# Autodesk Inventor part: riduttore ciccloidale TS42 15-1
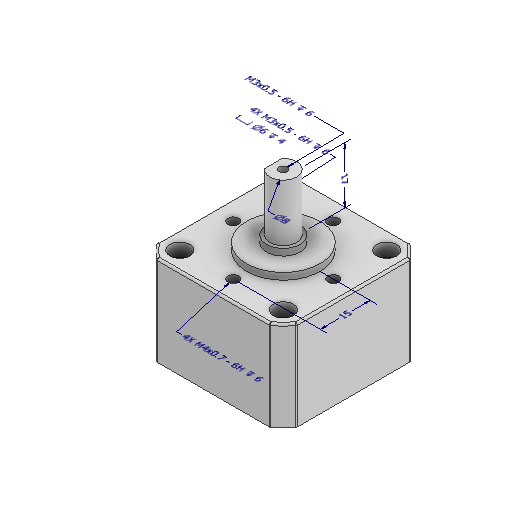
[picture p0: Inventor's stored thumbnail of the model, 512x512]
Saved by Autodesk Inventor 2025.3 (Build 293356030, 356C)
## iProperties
Created: 2026-03
Part Number: riduttore ciccloidale TS42 15-1
Material: Generico
Document SubType Name: Modeling
Designer: R5800u
Density: 1 g/cm^3
Appearance: Default
Author: R5800u
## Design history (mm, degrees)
node "Annotazioni"
  node "Quota diametro 1" dims "d11" = 17, "d58" = 8 (derived)
  node "Nota foro 1" dims "d11" = 17
  node "Nota foro 3" dims "d11" = 17
  node "Quota lineare 1" dims "d11" = 17, "d67" = 17 (derived)
  node "Quota lineare 2" dims "d11" = 17, "d69" = 15 (derived)
  node "Nota foro 4" dims "d11" = 17
  node "Quota lineare 3" dims "d11" = 17, "d73" = 27 (derived)
sketch "Schizzo1"
  geometry: L1 (21, -21)-(-21, -21); L2 (-21, -21)-(-21, 21); L3 (-21, 21)-(21, 21); L4 (21, 21)-(21, -21); L5 (21, -21)-(-21, 21); L6 (-21, -21)-(21, 21); 1 further point
  constraints: 12 end point, 2 midpoint, 2 parallel, 1 horizontal, 1 perpendicular
  dimensions: "d0" = 42 distance of L2.end L3.end; "d1" = 42 distance of L1.end L2.end
extrude "Estrusione1" new body sketch "Schizzo1" distance "d2" = 27; taper "d3" = 0 deg
sketch "Schizzo2"
  geometry: C1 r 11 at (0, 0); 1 further point
  constraints: 1 centre point, 1 coincident
  dimensions: "d4" = 22 diameter of C1
extrude "Estrusione2" join sketch "Schizzo2" distance "d5" = 2; taper "d6" = 0 deg
sketch "Schizzo3"
  geometry: C1 r 5 at (0, 0); 1 further point
  constraints: 1 centre point, 1 coincident
  dimensions: "d7" = 10 diameter of C1
extrude "Estrusione3" join sketch "Schizzo3" distance "d8" = 2; taper "d9" = 0 deg
sketch "Schizzo4"
  geometry: C1 r 4 at (0, 0); 1 further point
  constraints: 1 centre point, 1 coincident
  dimensions: "d10" = 8 diameter of C1
extrude "Estrusione4" join sketch "Schizzo4" distance "d11" = 17; taper "d12" = 0 deg
sketch "Schizzo5"
  geometry: L1 (-3, -2.646)-(-3, 2.646); A1 r 4 centre (0, 0) between (-3, -2.646) and (-3, 2.646) reference; 1 further point
  constraints: 2 end point, 2 point on circle, 1 vertical
  dimensions: "d13" = 3 distance from line of point (0, 0) L1
extrude "Estrusione5" cut sketch "Schizzo5" stored distance "d14" = 0; taper "d15" = 0 deg
sketch "Schizzo6"
  geometry: L1 (-21, -21)-(21, -21) reference; L2 (21, -21)-(21, 21) reference; L3 (21, 21)-(-21, 21) reference; L4 (-21, 21)-(-21, -21) reference; C1 r 27 at (0, 0); C2 r 11 at (0, 0) reference; A1 r 4 centre (0, 0) between (-3, -2.646) and (-3, 2.646) reference; 9 further points
  constraints: 1 centre point, 1 coincident
  dimensions: "d16" = 54 diameter of C1
extrude "Estrusione6" cut sketch "Schizzo6" extent not by distance; stored distance "d17" = 0; taper "d18" = 0 deg
sketch "Schizzo7" dims "d19" = 30
  geometry: L1 (0, 0)-(0, 15); A1 r 4 centre (0, 0) between (-3, -2.646) and (-3, 2.646) reference; 2 further points
  constraints: 2 coincident, 2 end point, 1 vertical, 1 vertical alignment, 2 other
hole "Foro1" sketch "Schizzo7" at (0, 15) diameter "d20" = 3.242; stored, may be unused: countersink angle "d24" = 90 deg, drill point angle "d26" = 118 deg; dims "d21" = 6, "d22" = 8, "d23" = 4.6, "d25" = 11.8
pattern_circular "Serie circolare1" dims angle "d28" = 360 deg
sketch "Schizzo8"
  geometry: L1 (15.5, -15.5)-(-15.5, -15.5); L2 (-15.5, -15.5)-(-15.5, 15.5); L3 (-15.5, 15.5)-(15.5, 15.5); L4 (15.5, 15.5)-(15.5, -15.5); L5 (15.5, -15.5)-(-15.5, 15.5); L6 (-15.5, -15.5)-(15.5, 15.5); C1 r 11 at (0, 0) reference; 1 further point
  constraints: 12 end point, 2 midpoint, 2 parallel, 1 horizontal, 1 perpendicular
  dimensions: "d30" = 31 distance of L2.end L3.end; "d31" = 31 distance of L1.end L2.end
sketch "Schizzo9"
  geometry: 1 further point
hole "Foro2" sketch "Schizzo9" at (0, 0) diameter "d32" = 2.459; stored, may be unused: countersink angle "d36" = 90 deg, drill point angle "d38" = 118 deg; dims "d33" = 6, "d34" = 4, "d35" = 2, "d37" = 8.8
hole "Foro3" sketch "Schizzo8" diameter "d39" = 2.459; stored, may be unused: countersink angle "d43" = 90 deg, drill point angle "d45" = 118 deg; dims "d40" = 6, "d41" = 6, "d42" = 4, "d44" = 8.8
fillet "Raccordo1" dims "d46" = 0.6
sketch "Schizzo10"
  geometry: C1 r 1.23 at (0, 0) reference; C2 r 11 at (0, 0); 1 further point
  constraints: 1 centre point, 1 coincident
  dimensions: "d47" = 22 diameter of C2
extrude "Estrusione7" cut sketch "Schizzo10" distance "d48" = 2; taper "d49" = 0 deg
sketch "Schizzo11"
  geometry: C1 r 11 at (0, 0) reference; 2 further points
  constraints: 1 coincident
hole "Foro4" sketch "Schizzo11" at (0, 0) diameter "d50" = 5; stored, may be unused: countersink angle "d54" = 90 deg, drill point angle "d56" = 118 deg; dims "d51" = 6, "d52" = 8, "d53" = 4.6, "d55" = 10
node "Solido1"
node "Linea chiusa proiettata1"
other parameters: "d57" = 21.47945 (derived), "d59" = 47.2619 (derived), "d63" = 51.85629 (derived), "d65" = 5.70964 (derived), "d66" = 7.51898 (derived), "d68" = 2.45787 (derived), "d70" = 44.83119 (derived), "d72" = 3.68505 (derived)
